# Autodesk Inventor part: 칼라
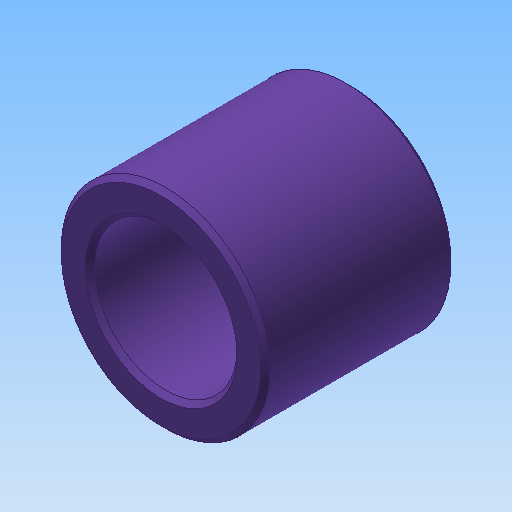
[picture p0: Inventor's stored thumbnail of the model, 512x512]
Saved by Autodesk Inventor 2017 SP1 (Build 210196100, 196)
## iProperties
Created: 2015-09
Part Number: 칼라
Document SubType Name: Modeling
Designer: mduedu
Density: 1 g/cm^3
Material: 스테인리스강
Appearance: 보라색
Author: mduedu
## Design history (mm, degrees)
node "작업 평면1"
node "작업 평면2"
sketch "스케치1"
  geometry: C1 r 7.5 at (0, 0); C2 r 11 at (0, 0); 1 further point
  constraints: 2 centre point, 2 coincident
  dimensions: "d0" = 15 diameter of C1; "d1" = 22 diameter of C2
extrude "돌출1" new body sketch "스케치1" distance "d2" = 20; taper "d3" = 0 deg
chamfer "모따기1" distance "d4" = 0.5; stored, may be unused: second distance "d5" = 2, angle "d6" = 45 deg
node "솔리드1"
